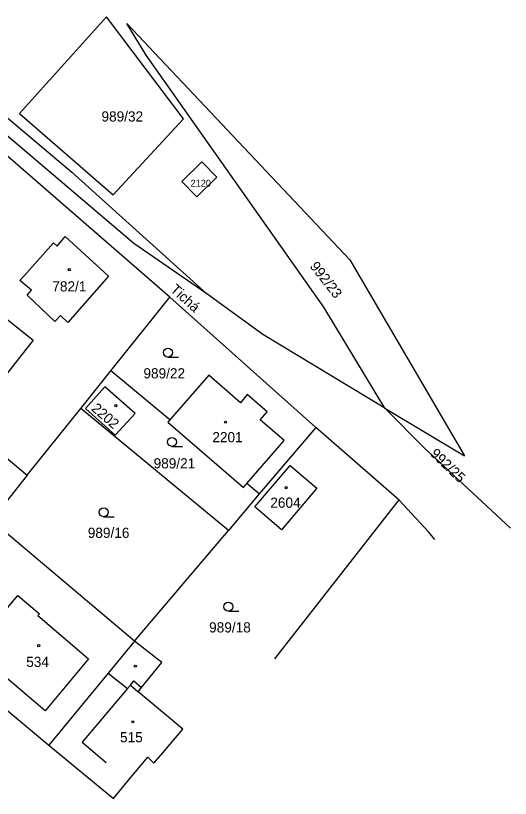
# Model space of a CAD drawing. Extents: x -793666 to -785424, y -1118958 to -1108761.
# Drawn here: x -791857.2 to -791774.6, y -1109774.8 to -1109644.2 of the extents above; entities that cross this region are included whole.
import ezdxf

# ---------------------------------------------------------------- set-up
doc = ezdxf.new("R2010")
doc.units = 0
for name, color, linetype in [('Hranice parcel', 7, 'Continuous'), ('Parcelní čísla', 7, 'Continuous'), ('Pop  PČ popisy', 7, 'Continuous'), ('Vnitřní kresba', 7, 'Continuous'), ('Značky budov', 7, 'Continuous'), ('Značky kultur', 7, 'Continuous')]:
    doc.layers.add(name, color=color, linetype=linetype)

msp = doc.modelspace()

# ---------------------------------------------------------------- linework, layer by layer
at = {"layer": 'Hranice parcel'}
for p, q in [((-791831.46, -1109691.13), (-791861.64, -1109664.97)), ((-791841.34, -1109703.45), (-791831.46, -1109691.13)), ((-791807.11, -1109712.92), (-791831.46, -1109691.13)), ((-791854.32, -1109698.31), (-791865.49, -1109712.41)), ((-791846.36, -1109709.71), (-791841.34, -1109703.45)), ((-791831.45, -1109711.63), (-791841.34, -1109703.45)), ((-791795.58, -1109709.65), (-791782.23, -1109717.64)), ((-791855.28, -1109720.85), (-791846.36, -1109709.71)), ((-791821.67, -1109730.06), (-791846.36, -1109709.71)), ((-791865.49, -1109712.41), (-791855.28, -1109720.85)), ((-791807.11, -1109712.92), (-791816.54, -1109723.96)), ((-791793.19, -1109725), (-791807.11, -1109712.92)), ((-791855.28, -1109720.85), (-791861.3, -1109728.39)), ((-791816.54, -1109723.96), (-791818.62, -1109722.24)), ((-791816.54, -1109723.96), (-791821.67, -1109730.06)), ((-791837.39, -1109748.55), (-791861.3, -1109728.39)), ((-791837.39, -1109748.55), (-791821.67, -1109730.06)), ((-791851.69, -1109765.91), (-791840.9, -1109774.79))]:
    msp.add_line(p, q, dxfattribs=at)
for points in [[(-791936.4, -1109607.05), (-791911, -1109616.98), (-791847.86, -1109670.26), (-791825.29, -1109690.56)], [(-791825.29, -1109690.56), (-791837.48, -1109682.19), (-791913.92, -1109617.19), (-791930.18, -1109620.63)], [(-791856.6, -1109660.48), (-791840.96, -1109674.06), (-791829.18, -1109661.4), (-791842.08, -1109644.36), (-791856.6, -1109660.48)], [(-791838.65, -1109645.44), (-791801.39, -1109684.93), (-791782.23, -1109717.64)], [(-791795.58, -1109709.65), (-791805.74, -1109692.83), (-791835.4, -1109650.78), (-791838.65, -1109645.44)], [(-791861.64, -1109664.97), (-791875.21, -1109681.64), (-791867.24, -1109688), (-791860.55, -1109693.34), (-791854.32, -1109698.31)], [(-791826.94, -1109674.41), (-791823.6, -1109671.11), (-791826.11, -1109668.56), (-791829.49, -1109671.86), (-791826.94, -1109674.41)], [(-791795.58, -1109709.65), (-791815.93, -1109697.37), (-791825.29, -1109690.56)], [(-791818.62, -1109722.24), (-791812.36, -1109715.04), (-791816.36, -1109711.61), (-791815.21, -1109710.27), (-791818.57, -1109707.41), (-791819.67, -1109708.76), (-791824.97, -1109704.18), (-791831.45, -1109711.63)], [(-791842.33, -1109706.1), (-791845.58, -1109709.73), (-791840.61, -1109714.18), (-791837.26, -1109710.54), (-791842.33, -1109706.1)], [(-791774.59, -1109729.68), (-791788.88, -1109716.38), (-791795.58, -1109709.65)], [(-791831.45, -1109711.63), (-791831.79, -1109712.02), (-791819.19, -1109722.9), (-791818.62, -1109722.24)], [(-791811.38, -1109719.23), (-791806.93, -1109723.03), (-791812.8, -1109729.97), (-791817.3, -1109726.15), (-791811.38, -1109719.23)], [(-791813.95, -1109751.53), (-791793.56, -1109725.47), (-791793.19, -1109725)], [(-791787.2, -1109731.61), (-791788.26, -1109730.31), (-791793.19, -1109725)], [(-791877.07, -1109748.13), (-791867.13, -1109753.04), (-791851.69, -1109765.91)], [(-791837.39, -1109748.55), (-791841.78, -1109753.88), (-791851.69, -1109765.91)], [(-791840.9, -1109774.79), (-791838.36, -1109771.74), (-791835.17, -1109767.93), (-791834.14, -1109768.94), (-791832.65, -1109767.19), (-791829.29, -1109763.26), (-791835.75, -1109757.84), (-791836.76, -1109756.99), (-791836.19, -1109756.3), (-791832.81, -1109752.13), (-791837.39, -1109748.55)]]:
    msp.add_lwpolyline(points, dxfattribs=at)
at = {"layer": 'Vnitřní kresba'}
for p, q in [((-791855.36, -1109687.06), (-791850.93, -1109682.05)), ((-791850.93, -1109682.05), (-791850.29, -1109682.61)), ((-791850.29, -1109682.61), (-791848.97, -1109681)), ((-791848.97, -1109681), (-791841.7, -1109687.61)), ((-791856.52, -1109688.38), (-791855.36, -1109687.06)), ((-791854.56, -1109689.99), (-791856.52, -1109688.38)), ((-791841.7, -1109687.61), (-791848.52, -1109695.39)), ((-791855.33, -1109690.8), (-791854.56, -1109689.99)), ((-791850.67, -1109695.2), (-791855.33, -1109690.8)), ((-791849.75, -1109694.23), (-791850.67, -1109695.2)), ((-791848.52, -1109695.39), (-791849.75, -1109694.23)), ((-791862.67, -1109747.82), (-791856.87, -1109740.94)), ((-791856.87, -1109740.94), (-791853.25, -1109743.97)), ((-791853.25, -1109743.97), (-791853.55, -1109744.29)), ((-791853.55, -1109744.29), (-791845.08, -1109751.48)), ((-791845.08, -1109751.48), (-791852.28, -1109760.19)), ((-791852.28, -1109760.19), (-791859.87, -1109753.78)), ((-791841.78, -1109753.88), (-791838.55, -1109756.46)), ((-791838.07, -1109755.89), (-791837.48, -1109755.19)), ((-791837.48, -1109755.19), (-791836.19, -1109756.3)), ((-791838.55, -1109756.46), (-791846.14, -1109765.39)), ((-791838.55, -1109756.46), (-791838.07, -1109755.89)), ((-791838.07, -1109755.89), (-791836.76, -1109756.99)), ((-791846.14, -1109765.39), (-791842.09, -1109768.79))]:
    msp.add_line(p, q, dxfattribs=at)
at = {"layer": 'Značky budov'}
for centre in [(-791848.27, -1109686.55), (-791840.49, -1109709.25), (-791822.18, -1109711.99), (-791812.03, -1109722.93), (-791853.39, -1109749.3), (-791837.24, -1109752.74), (-791837.65, -1109762.01)]:
    msp.add_circle(centre, 0.175, dxfattribs=at)
at = {"layer": 'Značky kultur'}
for p, q in [((-791831.8, -1109701.14), (-791830.05, -1109701.14)), ((-791831.13, -1109716.04), (-791829.38, -1109716.04)), ((-791842.53, -1109727.78), (-791840.78, -1109727.78)), ((-791821.7, -1109743.56), (-791819.95, -1109743.56))]:
    msp.add_line(p, q, dxfattribs=at)
for centre in [(-791831.8, -1109700.39), (-791831.13, -1109715.29), (-791842.53, -1109727.03), (-791821.7, -1109742.81)]:
    msp.add_circle(centre, 0.75, dxfattribs=at)

# ---------------------------------------------------------------- texts
at = {"layer": 'Parcelní čísla'}
for s, height, p in [('989/32', 1.7, (-791842.89, -1109661.83)), ('2120', 1.14, (-791828, -1109672.69)), ('782/1', 1.7, (-791851.1, -1109690.19)), ('989/22', 1.7, (-791835.88, -1109704.7)), ('2201', 1.7, (-791824.37, -1109715.36)), ('989/21', 1.7, (-791834.18, -1109719.72)), ('2604', 1.7, (-791814.69, -1109726.29)), ('989/16', 1.7, (-791845.18, -1109731.32)), ('989/18', 1.7, (-791824.91, -1109747.1)), ('534', 1.7, (-791855.46, -1109752.86)), ('515', 1.7, (-791839.79, -1109765.43))]:
    msp.add_text(s, height=height, dxfattribs=at).set_placement(p)
for s, rotation, p in [('992/23', 308, (-791808.17, -1109686.02)), ('2202', 319, (-791844.7, -1109709.93)), ('992/25', 316, (-791788.1, -1109717.42))]:
    msp.add_text(s, height=1.7, rotation=rotation, dxfattribs=at).set_placement(p)
at = {"layer": 'Pop  PČ popisy'}
msp.add_text('Tichá', height=1.7, rotation=318, dxfattribs=at).set_placement((-791831.52, -1109690.06))

doc.saveas('drawing.dxf')
